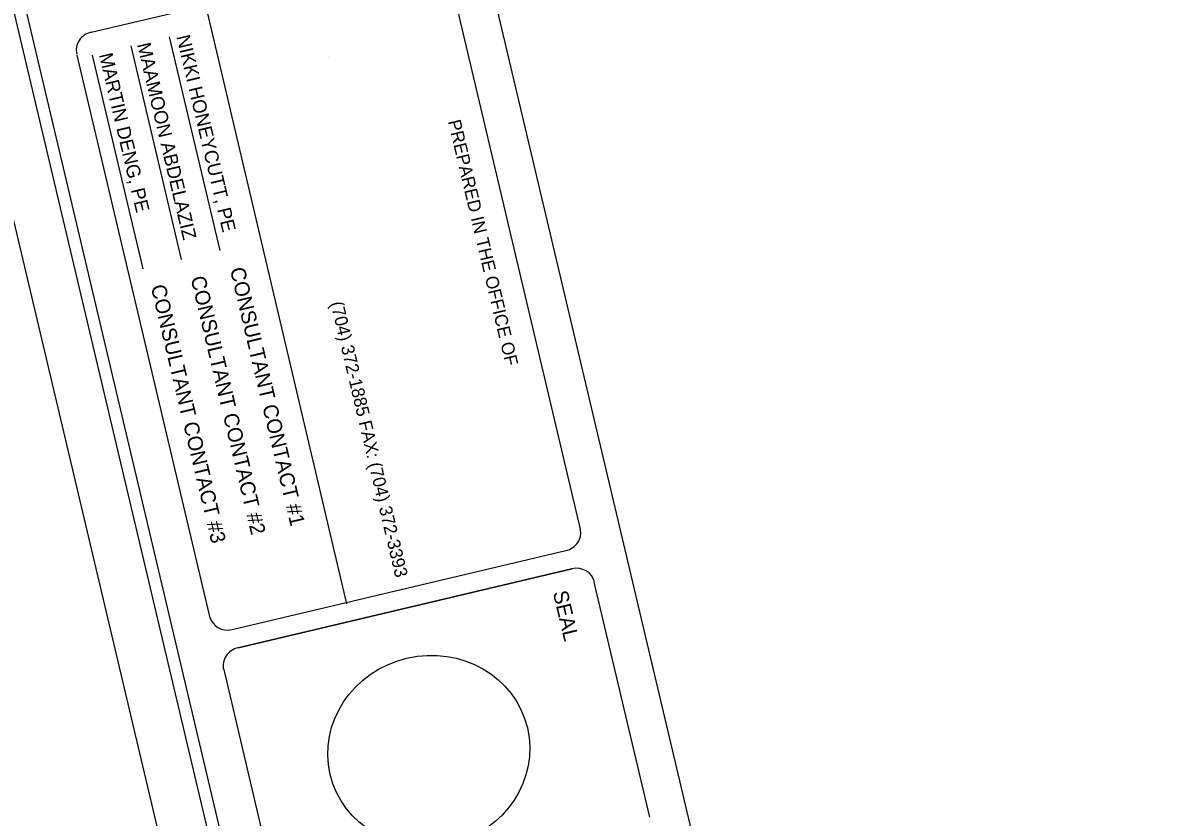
# Model space of a CAD drawing. Extents: x 1439200 to 1642353, y 394562 to 606444.
# Drawn here: x 1440332 to 1442416, y 599535 to 600981 of the extents above; entities that cross this region are included whole.
import ezdxf

# ---------------------------------------------------------------- set-up
doc = ezdxf.new("R2010")
doc.units = 0
doc.layers.add('Level 43', color=7, linetype='Continuous')
doc.layers.add('Water Line Text and Text Box and Leader Line (St)', color=7, linetype='Continuous')

msp = doc.modelspace()

# ---------------------------------------------------------------- linework, layer by layer
at = {"layer": 'Level 43'}
for p, q in [((1440363.8, 604519.2), (1441803.1, 598439.2)), ((1440456, 600964.1), (1441063.7, 601107.2)), ((1441105, 601083.4), (1441347.1, 600059.3)), ((1440664.9, 601010.8), (1440921.4, 599923.4)), ((1440658, 600977.6), (1440658, 600977.6)), ((1440528.1, 600939.2), (1440620.2, 600550)), ((1440598.2, 600955.8), (1440690.3, 600566.6)), ((1440430, 600922.1), (1440671.6, 599900.3)), ((1440457.9, 600922.6), (1440550.1, 600533.4)), ((1440888.2, 600919.1), (1440888.2, 600919.1)), ((1440713, 599876.3), (1441321, 600020.2)), ((1441332, 599987.1), (1440724, 599843.3)), ((1440724, 599843.3), (1441332, 599987.1)), ((1441332, 599987.1), (1440724, 599843.3)), ((1441372.2, 599962.8), (1441473.3, 599534.8)), ((1440697.6, 599803.4), (1440798.6, 599373.6))]:
    msp.add_line(p, q, dxfattribs=at)
msp.add_lwpolyline([(1445632.9, 599164.9), (1443909.8, 606443.8), (1439200, 605328.8), (1440923.1, 598050)], close=True, dxfattribs=at)
msp.add_lwpolyline([(1439494.5, 604562.1), (1440994.6, 598225.2)], dxfattribs=at)
for centre, major_axis, ratio, start_param, end_param in [((1440463.5, 600932.3), (33.8, 8), 0.941469, 1.570198, 3.141359), ((1441313.5, 600051.5), (33.8, 8), 0.930867, 4.711814, 6.283034), ((1441339.3, 599955.1), (33.8, 8), 0.941469, 6.283006, 7.85338), ((1440705.7, 599908), (-33.8, -8), 0.941469, 6.282951, 7.853377), ((1440731.2, 599811.3), (-33.8, -8), 0.941469, 4.711788, 6.282949)]:
    msp.add_ellipse(centre, major_axis=major_axis, ratio=ratio, start_param=start_param, end_param=end_param, dxfattribs=at)
msp.add_ellipse((1441071.2, 599655), major_axis=(-179.6, -42.5), ratio=0.941469, dxfattribs=at)
at = {"layer": 'Water Line Text and Text Box and Leader Line (St)'}
msp.add_lwpolyline([(1439298.8, 605293.4), (1440988.4, 598155.9), (1445527, 599230.3), (1443837.3, 606367.8)], close=True, dxfattribs=at)

# ---------------------------------------------------------------- texts
at = {"layer": 'Level 43'}
for s, height, p in [('NIKKI HONEYCUTT, PE', 25, (1440611.1, 600956.2)), ('MAAMOON ABDELAZIZ', 25, (1440539.5, 600942)), ('MARTIN DENG, PE', 25, (1440470.1, 600923.2)), ('PREPARED IN THE OFFICE OF', 23.423, (1441106, 600801.9)), ('CONSULTANT CONTACT #2', 27.199, (1440637, 600516.8)), ('CONSULTANT CONTACT #1', 27.199, (1440708.7, 600532.7)), ('CONSULTANT CONTACT #3', 27.199, (1440564.5, 600501.2)), ('(704) 372-1885 FAX: (704) 372-3393', 23.423, (1440892.1, 600471)), ('SEAL ', 27.2, (1441297.1, 599943.8))]:
    msp.add_text(s, height=height, rotation=283.3038, dxfattribs=at).set_placement(p)

doc.saveas('drawing.dxf')
